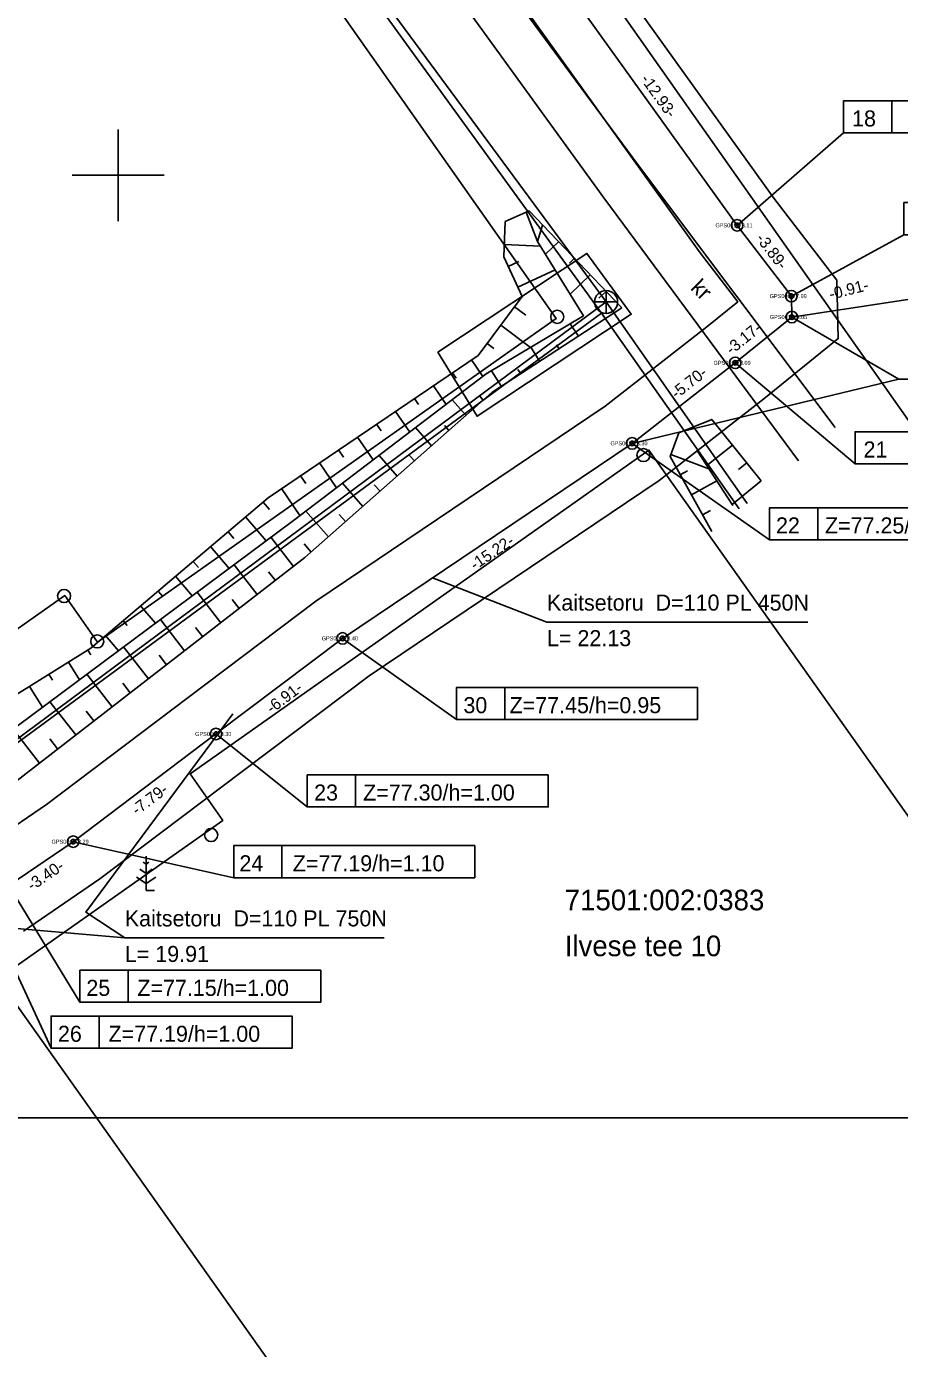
# Model space of a CAD drawing. Extents: x 593727 to 603084, y 6472047 to 6482364.
# Drawn here: x 595996 to 596034.1, y 6473948.9 to 6474006.5 of the extents above; entities that cross this region are included whole.
import ezdxf

# ---------------------------------------------------------------- set-up
doc = ezdxf.new("R2010")
doc.units = 0
for name, color, linetype in [('HALJASTUS', 7, 'Continuous'), ('JOONSIDE', 7, 'Continuous'), ('KKAEV', 7, 'Continuous'), ('KOORDPUNKT', 7, 'Continuous'), ('KTRASS', 7, 'Continuous'), ('MOOTKORG-EH2000', 7, 'Continuous'), ('MOOTMPUNKT', 7, 'Continuous'), ('MOOTNR', 7, 'Continuous'), ('MOOTPIIR', 7, 'Continuous'), ('MPKAABEL', 7, 'Continuous'), ('PIIR', 7, 'Continuous'), ('PIIRIMLEITUD', 7, 'Continuous'), ('PUU', 7, 'Continuous'), ('RELJEEF', 7, 'Continuous'), ('TEE', 7, 'Continuous'), ('VORK', 7, 'Continuous'), ('VORMISTUS', 7, 'Continuous'), ('VTRASS', 7, 'Continuous')]:
    doc.layers.add(name, color=color, linetype=linetype)

msp = doc.modelspace()

# ---------------------------------------------------------------- linework, layer by layer
at = {"layer": 'HALJASTUS'}
msp.add_lwpolyline([(596013.933, 6473992.287), (596015.646, 6473989.496), (596022.365, 6473993.944), (596020.433, 6473996.592)], close=True, dxfattribs=at)
at = {"layer": 'KKAEV'}
for p, q in [((596020.768, 6473994.477), (596021.768, 6473994.477)), ((596021.268, 6473993.977), (596021.268, 6473994.977))]:
    msp.add_line(p, q, dxfattribs=at)
msp.add_circle((596021.268, 6473994.477), 0.5, dxfattribs=at)
at = {"layer": 'KOORDPUNKT'}
for points in [[(596026.978, 6473997.816), (596031.622, 6474001.846), (596042.122, 6474001.846), (596042.122, 6474003.246), (596031.622, 6474003.246), (596031.622, 6474001.846)], [(596033.722, 6474001.846), (596033.722, 6474003.246)], [(596029.342, 6473994.732), (596034.252, 6473997.407), (596044.752, 6473997.407), (596044.752, 6473998.807), (596034.252, 6473998.807), (596034.252, 6473997.407)], [(596029.364, 6473993.819), (596035.283, 6473994.721), (596045.783, 6473994.721), (596045.783, 6473996.121), (596035.283, 6473996.121), (596035.283, 6473994.721)], [(596026.896, 6473991.824), (596032.122, 6473987.416), (596042.622, 6473987.416), (596042.622, 6473988.816), (596032.122, 6473988.816), (596032.122, 6473987.416)], [(596022.401, 6473988.312), (596028.392, 6473984.107), (596038.892, 6473984.107), (596038.892, 6473985.507), (596028.392, 6473985.507), (596028.392, 6473984.107)], [(596030.492, 6473984.107), (596030.492, 6473985.507)], [(596009.78, 6473979.811), (596014.749, 6473976.271), (596025.249, 6473976.271), (596025.249, 6473977.671), (596014.749, 6473977.671), (596014.749, 6473976.271)], [(596016.849, 6473976.271), (596016.849, 6473977.671)], [(596004.261, 6473975.645), (596008.242, 6473972.462), (596018.742, 6473972.462), (596018.742, 6473973.862), (596008.242, 6473973.862), (596008.242, 6473972.462)], [(596010.342, 6473972.462), (596010.342, 6473973.862)], [(595998.04, 6473970.949), (596005.038, 6473969.378), (596015.538, 6473969.378), (596015.538, 6473970.778), (596005.038, 6473970.778), (596005.038, 6473969.378)], [(596007.138, 6473969.378), (596007.138, 6473970.778)], [(595993.808, 6473968.997), (595997.076, 6473961.946), (596007.576, 6473961.946), (596007.576, 6473963.346), (595997.076, 6473963.346), (595997.076, 6473961.946)], [(595995.228, 6473969.033), (595998.331, 6473963.948), (596008.831, 6473963.948), (596008.831, 6473965.348), (595998.331, 6473965.348), (595998.331, 6473963.948)], [(596000.431, 6473963.948), (596000.431, 6473965.348)], [(595999.176, 6473961.946), (595999.176, 6473963.346)]]:
    msp.add_lwpolyline(points, dxfattribs=at)
for centre, radius in [((596026.978, 6473997.816), 0.25), ((596026.978, 6473997.816), 0.025), ((596026.978, 6473997.816), 0.0221), ((596026.978, 6473997.816), 0.0191), ((596026.978, 6473997.816), 0.0161), ((596026.978, 6473997.816), 0.0132), ((596026.978, 6473997.816), 0.0102), ((596026.978, 6473997.816), 0.00726), ((596026.978, 6473997.816), 0.0043), ((596029.342, 6473994.732), 0.25), ((596029.342, 6473994.732), 0.025), ((596029.342, 6473994.732), 0.0221), ((596029.342, 6473994.732), 0.0191), ((596029.342, 6473994.732), 0.0161), ((596029.342, 6473994.732), 0.0132), ((596029.342, 6473994.732), 0.0102), ((596029.342, 6473994.732), 0.00726), ((596029.342, 6473994.732), 0.0043), ((596029.364, 6473993.819), 0.25), ((596029.364, 6473993.819), 0.025), ((596029.364, 6473993.819), 0.0221), ((596029.364, 6473993.819), 0.0191), ((596029.364, 6473993.819), 0.0161), ((596029.364, 6473993.819), 0.0132), ((596029.364, 6473993.819), 0.0102), ((596029.364, 6473993.819), 0.00726), ((596029.364, 6473993.819), 0.0043), ((596026.896, 6473991.824), 0.25), ((596026.896, 6473991.824), 0.025), ((596026.896, 6473991.824), 0.0221), ((596026.896, 6473991.824), 0.0191), ((596026.896, 6473991.824), 0.0161), ((596026.896, 6473991.824), 0.0132), ((596026.896, 6473991.824), 0.0102), ((596026.896, 6473991.824), 0.00726), ((596026.896, 6473991.824), 0.0043), ((596022.401, 6473988.312), 0.25), ((596022.401, 6473988.312), 0.025), ((596022.401, 6473988.312), 0.0221), ((596022.401, 6473988.312), 0.0191), ((596022.401, 6473988.312), 0.0161), ((596022.401, 6473988.312), 0.0132), ((596022.401, 6473988.312), 0.0102), ((596022.401, 6473988.312), 0.00726), ((596022.401, 6473988.312), 0.0043), ((596009.78, 6473979.811), 0.25), ((596009.78, 6473979.811), 0.025), ((596009.78, 6473979.811), 0.0221), ((596009.78, 6473979.811), 0.0191), ((596009.78, 6473979.811), 0.0161), ((596009.78, 6473979.811), 0.0132), ((596009.78, 6473979.811), 0.0102), ((596009.78, 6473979.811), 0.00726), ((596009.78, 6473979.811), 0.0043), ((596004.261, 6473975.645), 0.25), ((596004.261, 6473975.645), 0.025), ((596004.261, 6473975.645), 0.0221), ((596004.261, 6473975.645), 0.0191), ((596004.261, 6473975.645), 0.0161), ((596004.261, 6473975.645), 0.0132), ((596004.261, 6473975.645), 0.0102), ((596004.261, 6473975.645), 0.00726), ((596004.261, 6473975.645), 0.0043), ((595998.04, 6473970.949), 0.25), ((595998.04, 6473970.949), 0.025), ((595998.04, 6473970.949), 0.0221), ((595998.04, 6473970.949), 0.0191), ((595998.04, 6473970.949), 0.0161), ((595998.04, 6473970.949), 0.0132), ((595998.04, 6473970.949), 0.0102), ((595998.04, 6473970.949), 0.00726), ((595998.04, 6473970.949), 0.0043)]:
    msp.add_circle(centre, radius, dxfattribs=at)
at = {"layer": 'KTRASS'}
for points in [[(596021.268, 6473994.477), (596009.8, 6474010.035), (595993.91, 6474032.584), (595992.815, 6474032.028)], [(595988.429, 6473973.193), (595992.154, 6473972.873), (596021.268, 6473994.477), (596027.413, 6473985.696)]]:
    msp.add_lwpolyline(points, dxfattribs=at)
at = {"layer": 'MOOTMPUNKT'}
for centre in [(596026.978, 6473997.816), (596029.342, 6473994.732), (596029.364, 6473993.819), (596026.896, 6473991.824), (596022.401, 6473988.312), (596009.78, 6473979.811), (596004.261, 6473975.645), (595998.04, 6473970.949)]:
    msp.add_circle(centre, 0.1, dxfattribs=at)
at = {"layer": 'MOOTPIIR'}
for points in [[(595995.868, 6473967.049), (595999.206, 6473969.324), (596005.466, 6473974.049), (596010.942, 6473978.182), (596023.577, 6473986.693), (596028.14, 6473990.258), (596031.387, 6473992.883), (596031.326, 6473995.432), (596028.584, 6473999.008), (596021.07, 6474009.473)], [(596017.808, 6474007.157), (596025.372, 6473996.624), (596027.009, 6473994.487), (596025.652, 6473993.39), (596021.225, 6473989.931), (596008.618, 6473981.44), (596003.056, 6473977.242), (595996.874, 6473972.574), (595994.603, 6473971.027)]]:
    msp.add_lwpolyline(points, dxfattribs=at)
at = {"layer": 'MPKAABEL'}
for points in [[(596014.463, 6474066.806), (596002.148, 6474057.419), (595998.723, 6474054.604), (595996.671, 6474051.87), (595996.141, 6474049.764), (595996.361, 6474045.748), (595997.222, 6474041.549), (595998.968, 6474037.996), (596003.482, 6474031.514), (596011.528, 6474019.578), (596019.439, 6474008.315), (596026.978, 6473997.816), (596029.342, 6473994.732), (596029.364, 6473993.819)], [(595997.222, 6474041.549), (595998.968, 6474037.996), (596003.482, 6474031.514), (596011.528, 6474019.578), (596019.439, 6474008.315), (596026.978, 6473997.816), (596029.342, 6473994.732), (596029.364, 6473993.819), (596026.896, 6473991.824), (596022.401, 6473988.312), (596009.78, 6473979.811), (596004.261, 6473975.645), (595998.04, 6473970.949), (595995.228, 6473969.033), (595993.808, 6473968.997), (595992.272, 6473970.526), (595991.471, 6473971.588), (595989.417, 6473974.773), (595989.197, 6473975.301)], [(596029.364, 6473993.819), (596026.896, 6473991.824), (596022.401, 6473988.312)], [(596029.364, 6473993.819), (596034.033, 6473991.113), (596045.337, 6473991.113)], [(596022.401, 6473988.312), (596034.033, 6473991.113)], [(596022.401, 6473988.312), (596009.78, 6473979.811), (596004.261, 6473975.645)], [(596013.703, 6473982.453), (596018.69, 6473980.522), (596030.064, 6473980.522)], [(596004.996, 6473976.524), (595998.591, 6473967.872), (596000.288, 6473966.757), (596011.592, 6473966.757)], [(596004.261, 6473975.645), (595998.04, 6473970.949), (595995.228, 6473969.033), (595993.808, 6473968.997), (595992.272, 6473970.526), (595991.471, 6473971.588), (595989.417, 6473974.773)], [(595989.417, 6473974.773), (595990.171, 6473967.629), (596000.288, 6473966.757)]]:
    msp.add_lwpolyline(points, dxfattribs=at)
at = {"layer": 'PIIR'}
for points in [[(596066.57, 6473926.31), (596046.52, 6473955.01), (596023.13, 6473988.02), (596003.14, 6473973.91), (596004.56, 6473971.88), (595994.75, 6473964.97), (595991.31, 6473969.86), (595987.85, 6473974.77), (595997.67, 6473981.68), (595999.1, 6473979.65), (596019.09, 6473993.75), (595995.81, 6474026.85), (595974.94, 6474056.4)], [(595999.81, 6474054.43), (595999.85, 6474038.49), (596017.77, 6474013.02), (596039.91, 6473981.55), (596067.53, 6474000.96), (596066.09, 6474003.01), (596075.89, 6474009.92), (596079.35, 6474005.02), (596082.79, 6474000.11), (596072.98, 6473993.2), (596071.55, 6473995.25), (596043.93, 6473975.83), (596066.1, 6473944.35)]]:
    msp.add_lwpolyline(points, dxfattribs=at)
for points in [[(596017.77, 6474013.02), (596048.7, 6474034.81), (596055.18, 6474039.36), (596075.89, 6474009.92), (596066.09, 6474003.01), (596067.53, 6474000.96), (596039.91, 6473981.55)], [(595965.97, 6474005.85), (595995.81, 6474026.85), (596019.09, 6473993.75), (595999.1, 6473979.65), (595997.67, 6473981.68), (595987.85, 6473974.77)], [(595994.75, 6473964.97), (596004.56, 6473971.88), (596003.14, 6473973.91), (596023.13, 6473988.02), (596046.52, 6473955.01), (596016.68, 6473934.04)], [(595962.03, 6473949.48), (595963.77, 6473950.58), (595991.31, 6473969.86), (595994.75, 6473964.97), (596016.68, 6473934.04), (595975.1, 6473904.62), (595970.53, 6473901.86), (595972.52, 6473915.54), (595965.11, 6473943.08)]]:
    msp.add_lwpolyline(points, close=True, dxfattribs=at)
at = {"layer": 'PIIRIMLEITUD'}
for centre in [(596019.137, 6473993.829), (596022.893, 6473987.802), (595997.639, 6473981.66), (595999.087, 6473979.678), (596004.051, 6473971.242)]:
    msp.add_circle(centre, 0.285, dxfattribs=at)
at = {"layer": 'PUU'}
for p, q in [((596001.216, 6473970.318), (596001.216, 6473968.818)), ((596001.216, 6473969.568), (596000.949, 6473969.746)), ((596001.216, 6473969.968), (596001.092, 6473970.051)), ((596001.34, 6473970.051), (596001.216, 6473969.968)), ((596001.483, 6473969.746), (596001.216, 6473969.568)), ((596000.792, 6473969.407), (596001.216, 6473969.125)), ((596001.216, 6473969.125), (596001.64, 6473969.407)), ((596001.576, 6473968.818), (596001.216, 6473968.818))]:
    msp.add_line(p, q, dxfattribs=at)
at = {"layer": 'RELJEEF'}
for p, q in [((596017.779, 6473998.39), (596018.28, 6473997.118)), ((596018.501, 6473997.827), (596018.28, 6473997.118)), ((596016.826, 6473996.977), (596018.41, 6473996.907)), ((596019.192, 6473997.105), (596018.624, 6473996.561)), ((596017.002, 6473996.022), (596017.458, 6473996.234)), ((596019.883, 6473996.382), (596019.667, 6473996.175)), ((596017.423, 6473995.115), (596019.051, 6473995.871)), ((596020.575, 6473995.659), (596019.699, 6473994.822)), ((596021.266, 6473994.937), (596020.957, 6473994.641)), ((596017.281, 6473994.267), (596017.769, 6473993.902)), ((596016.682, 6473993.466), (596017.978, 6473992.497)), ((596020.058, 6473992.979), (596019.701, 6473993.528)), ((596016.084, 6473992.665), (596016.374, 6473992.448)), ((596018.382, 6473991.888), (596017.984, 6473992.5)), ((596019.22, 6473992.434), (596019.107, 6473992.608)), ((596015.404, 6473991.948), (596015.894, 6473991.225)), ((596014.576, 6473991.388), (596014.732, 6473991.157)), ((596016.705, 6473990.798), (596016.267, 6473991.472)), ((596017.543, 6473991.343), (596017.418, 6473991.536)), ((596013.748, 6473990.827), (596014.299, 6473990.013)), ((596012.92, 6473990.266), (596013.095, 6473990.009)), ((596015.162, 6473989.532), (596014.561, 6473990.212)), ((596015.911, 6473990.194), (596015.746, 6473990.382)), ((596012.092, 6473989.706), (596012.705, 6473988.801)), ((596011.264, 6473989.145), (596011.457, 6473988.86)), ((596013.663, 6473988.208), (596012.965, 6473988.998)), ((596014.412, 6473988.87), (596014.217, 6473989.091)), ((596010.436, 6473988.584), (596011.11, 6473987.589)), ((596026.774, 6473988.24), (596025.66, 6473987.341)), ((596009.608, 6473988.024), (596009.82, 6473987.711)), ((596012.164, 6473986.884), (596011.368, 6473987.785)), ((596012.913, 6473987.546), (596012.689, 6473987.8)), ((596024.085, 6473987.821), (596025.749, 6473987.204)), ((596008.78, 6473987.463), (596009.516, 6473986.377)), ((596024.497, 6473986.941), (596024.811, 6473987.116)), ((596027.402, 6473987.461), (596027.044, 6473987.172)), ((596007.952, 6473986.902), (596008.182, 6473986.563)), ((596010.665, 6473985.56), (596009.772, 6473986.571)), ((596011.414, 6473986.222), (596011.161, 6473986.509)), ((596024.984, 6473986.067), (596026.088, 6473986.682)), ((596028.03, 6473986.683), (596026.756, 6473985.655)), ((596007.124, 6473986.342), (596007.921, 6473985.164)), ((596006.315, 6473985.756), (596006.595, 6473985.427)), ((596009.166, 6473984.236), (596008.175, 6473985.358)), ((596025.47, 6473985.194), (596025.819, 6473985.388)), ((596005.553, 6473985.109), (596006.443, 6473984.06)), ((596009.915, 6473984.898), (596009.633, 6473985.218)), ((596004.79, 6473984.462), (596005.045, 6473984.162)), ((596007.64, 6473982.944), (596006.655, 6473984.218)), ((596004.028, 6473983.814), (596004.835, 6473982.864)), ((596008.416, 6473983.574), (596008.104, 6473983.928)), ((596003.265, 6473983.167), (596003.495, 6473982.897)), ((596006.059, 6473981.72), (596005.05, 6473983.024)), ((596002.503, 6473982.52), (596003.227, 6473981.667)), ((596006.849, 6473982.332), (596006.55, 6473982.719)), ((596001.741, 6473981.873), (596001.945, 6473981.632)), ((596004.477, 6473980.496), (596003.445, 6473981.83)), ((596000.978, 6473981.226), (596001.619, 6473980.471)), ((596005.268, 6473981.108), (596004.962, 6473981.504)), ((596000.216, 6473980.579), (596000.396, 6473980.367)), ((596002.895, 6473979.273), (596001.841, 6473980.635)), ((596003.686, 6473979.885), (596003.373, 6473980.289)), ((595999.453, 6473979.932), (596000.011, 6473979.274)), ((595998.678, 6473979.303), (595998.808, 6473979.094)), ((596001.313, 6473978.049), (596000.236, 6473979.441)), ((596002.104, 6473978.661), (596001.784, 6473979.074)), ((595997.829, 6473978.775), (595998.307, 6473978.006)), ((595996.98, 6473978.246), (595997.136, 6473977.995)), ((595999.731, 6473976.825), (595998.631, 6473978.247)), ((596000.522, 6473977.437), (596000.195, 6473977.859)), ((595996.131, 6473977.718), (595996.697, 6473976.808)), ((595998.149, 6473975.601), (595997.026, 6473977.053)), ((595998.94, 6473976.213), (595998.607, 6473976.644)), ((595996.567, 6473974.378), (595995.421, 6473975.859)), ((595997.358, 6473974.99), (595997.018, 6473975.429))]:
    msp.add_line(p, q, dxfattribs=at)
for points in [[(596021.957, 6473994.214), (596017.907, 6473998.448), (596016.871, 6473997.981), (596016.803, 6473996.451), (596017.612, 6473994.709), (596015.695, 6473992.145), (596006.538, 6473985.945), (595998.808, 6473979.384), (595991.844, 6473975.05), (595990.953, 6473975.27), (595988.912, 6473975.483), (595986.324, 6473974.36), (595986.259, 6473971.842), (595987.38, 6473969.63), (595988.837, 6473968.939), (595990.55, 6473969.569), (595990.941, 6473966.644), (595992.055, 6473966.06), (595993.12, 6473966.772), (595993.603, 6473968.719), (595993.385, 6473971.916), (596008.142, 6473983.332), (596016.283, 6473990.523), (596021.957, 6473994.214)], [(596018.28, 6473997.118), (596020.283, 6473993.877), (596016.041, 6473991.337), (596007.647, 6473984.956), (595991.153, 6473972.683), (595989.99, 6473973.637), (595988.649, 6473973.756), (595987.864, 6473973.014), (595988.647, 6473970.773), (595989.557, 6473970.474), (595991.864, 6473969.657), (595992.013, 6473967.189), (595991.913, 6473969.636), (595991.153, 6473972.683)], [(596028.03, 6473986.683), (596025.873, 6473989.357), (596024.437, 6473988.771), (596024.054, 6473987.738), (596025.876, 6473984.464)], [(596026.785, 6473985.611), (596025.218, 6473988.019)]]:
    msp.add_lwpolyline(points, dxfattribs=at)
at = {"layer": 'TEE'}
for points in [[(596031.92, 6474089.538), (596031.304, 6474086.654), (596029.381, 6474083.691), (596025.099, 6474079.23), (596019.083, 6474074.682), (596007.86, 6474067.339), (595996.337, 6474059.544), (595994.689, 6474057.913), (595992.598, 6474055.095), (595991.286, 6474052.246), (595990.709, 6474049.521), (595990.678, 6474045.813), (595991.744, 6474041.996), (595994.295, 6474036.613), (595996.116, 6474034.095), (596004.269, 6474022.484), (596012.454, 6474011.067), (596021.171, 6473999.009), (596029.659, 6473987.552)], [(596031.256, 6473989.002), (596022.629, 6474000.49), (596014.566, 6474011.418), (596005.949, 6474023.815), (595997.389, 6474035.698), (595994.514, 6474040.842), (595992.998, 6474044.834), (595992.861, 6474048.906), (595993.607, 6474052.227), (595995.052, 6474054.981), (595997.577, 6474057.706), (596008.43, 6474065.294), (596020.365, 6474072.528), (596025.712, 6474076.969), (596031.411, 6474082.45), (596033.754, 6474085.703), (596034.258, 6474088.185)]]:
    msp.add_lwpolyline(points, dxfattribs=at)
at = {"layer": 'VORK'}
for p, q in [((596000, 6474002), (596000, 6473998)), ((595998, 6474000), (596002, 6474000))]:
    msp.add_line(p, q, dxfattribs=at)
at = {"layer": 'VORMISTUS'}
msp.add_lwpolyline([(595935.65, 6473958.907), (595935.65, 6474102.407), (596133.15, 6474102.407), (596133.15, 6473958.907)], close=True, dxfattribs=at)
at = {"layer": 'VTRASS'}
for points in [[(596021.07, 6473993.982), (596009.847, 6474009.478), (596008.326, 6474008.33)], [(595991.746, 6473968.528), (595991.823, 6473972.49), (596021.07, 6473993.982), (596027.071, 6473985.453)]]:
    msp.add_lwpolyline(points, dxfattribs=at)

# ---------------------------------------------------------------- texts
at = {"layer": 'JOONSIDE'}
for s, rotation, p in [('-12.93-', 305.68093, (596022.747, 6474004.18)), ('-3.89-', 307.4715, (596027.77, 6473997.235)), ('-0.91-', 14.33247, (596031.055, 6473994.566)), ('-3.17-', 38.95023, (596026.731, 6473992.15)), ('-5.70-', 38.00096, (596024.338, 6473990.231)), ('-15.22-', 33.96263, (596015.549, 6473982.762)), ('-6.91-', 37.04752, (596006.69, 6473976.507)), ('-7.79-', 37.04752, (596000.82, 6473972.076)), ('-3.40-', 34.26917, (595996.244, 6473968.787))]:
    msp.add_text(s, height=0.5, rotation=rotation, dxfattribs=at).set_placement(p)
at = {"layer": 'KOORDPUNKT'}
for s, p in [('18', (596031.989, 6474002.126)), ('21', (596032.489, 6473987.696)), ('22', (596028.672, 6473984.387)), ('Z=77.25/h=1.05', (596030.807, 6473984.387)), ('30', (596015.046, 6473976.551)), ('Z=77.45/h=0.95', (596017.059, 6473976.551)), ('23', (596008.54, 6473972.742)), ('Z=77.30/h=1.00', (596010.675, 6473972.742)), ('24', (596005.283, 6473969.658)), ('Z=77.19/h=1.10', (596007.61, 6473969.658)), ('25', (595998.611, 6473964.228)), ('Z=77.15/h=1.00', (596000.834, 6473964.228)), ('26', (595997.373, 6473962.226)), ('Z=77.19/h=1.00', (595999.578, 6473962.226))]:
    msp.add_text(s, height=0.7, dxfattribs=at).set_placement(p)
at = {"layer": 'MOOTKORG-EH2000'}
for s, p in [(' 78.11', (596026.978, 6473997.728)), (' 77.99', (596029.342, 6473994.644)), (' 78.05', (596029.364, 6473993.731)), (' 78.09', (596026.896, 6473991.736)), (' 78.30', (596022.401, 6473988.225)), (' 78.40', (596009.78, 6473979.724)), (' 78.30', (596004.261, 6473975.558)), (' 78.29', (595998.04, 6473970.861))]:
    msp.add_text(s, height=0.175, dxfattribs=at).set_placement(p)
at = {"layer": 'MOOTNR'}
for s, p in [('GPS0016 ', (596026.033, 6473997.728)), ('GPS0015 ', (596028.397, 6473994.644)), ('GPS0014 ', (596028.402, 6473993.731)), ('GPS0013 ', (596025.951, 6473991.736)), ('GPS0012 ', (596021.456, 6473988.225)), ('GPS0011 ', (596008.87, 6473979.724)), ('GPS0011 ', (596003.351, 6473975.558)), ('GPS0010 ', (595997.095, 6473970.861))]:
    msp.add_text(s, height=0.175, dxfattribs=at).set_placement(p)
at = {"layer": 'MPKAABEL'}
for s, p in [('Kaitsetoru  D=110 PL 450N', (596018.69, 6473981.022)), ('L= 22.13', (596018.69, 6473979.472)), ('Kaitsetoru  D=110 PL 750N', (596000.288, 6473967.257)), ('L= 19.91', (596000.288, 6473965.707))]:
    msp.add_text(s, height=0.7, dxfattribs=at).set_placement(p)
at = {"layer": 'PIIR'}
for s, p in [('71501:002:0383', (596019.463, 6473967.958)), ('Ilvese tee 10', (596019.463, 6473965.958))]:
    msp.add_text(s, height=0.9, dxfattribs=at).set_placement(p)
at = {"layer": 'TEE'}
msp.add_text('kr', height=0.7, rotation=315.49158, dxfattribs=at).set_placement((596024.905, 6473995.046))

doc.saveas('drawing.dxf')
